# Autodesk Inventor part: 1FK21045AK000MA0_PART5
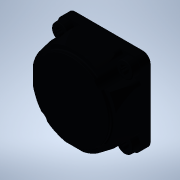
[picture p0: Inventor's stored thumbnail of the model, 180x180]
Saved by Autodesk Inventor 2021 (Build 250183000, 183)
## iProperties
Created: 2025-04
Part Number: 1FK21045AK000MA0_PART5
Material: Generic
Catalog Web Link: www.3dfindit.com
Description: -Servo synchronous motor
Document SubType Name: Modeling
Designer: psAdmin
Mass: 3.92604 g
Surface Area: 17.9521 cm^2
Volume: 3.92604 cm^3
Density: 1 g/cm^3
Appearance: PSOLRGB-48-56-69
Category: PARTsolutions
Title: 1FK21045AK000MA0_PART5
Author: Cadenas PARTsolutions
Comments: Servo synchronous motor
Sending System: PARTsolutions
Preprocessor: ST-DEVELOPER v19.3
PSOL_IDENT_0: {$CADENAS_DATA/23d-libs/siemens_ag/_cat_/3d/2f/1fk21045ak000ma0.prj},213 {VTYP=3D},{NB=1FK21045AK000
PSOL_IDENT_1: MA0_PART5},{LINA=1FK21045AK000MA0_PART5},{NN=1FK21045AK000MA0_PART5},{NOPRJ=TRUE},{DATE=19.08.2025 1
PSOL_IDENT_2: 4:00:34},{GEOMDATE=30.07.2025 02:01:24},{VERSION=},{LINEID=10},{WBVAR=},{WBNUMERIC=}  {NB=1FK21045AK
PSOL_IDENT_3: 000MA0_PART5},{LINA=1FK21045AK000MA0_PART5},{KT=DUMMY},{PREVIEW=../../../_pool_/a9/69/p_d211_xx_0081
PSOL_IDENT_4: 8j.png},{DESCSHORT=SIMOTICS S-1FK2 HD, SINAMICS S210 3AC 400V-480V, 1.7 Nm, 6000 rpm},{DESCLONG=SIMO
PSOL_IDENT_5: TICS S-1FK2 HD servo motor M0=2.4 Nm; PN = 1.07 kW at nN=6000 rpm (380-480 V); PN = 0.75 kW at nN=30
PSOL_IDENT_6: 00 rpm (200-240 V); degree of protection IP64; cylindrical shaft D19x40mm; absolute encoder 22-bit +
PSOL_IDENT_7: 12-bit multiturn (encoder AM22DQC); with OCC interface; plug size M17, rotatable; SIMOTICS S-1FK2 s
PSOL_IDENT_8: ervomotorfor a wide range of uses in industrial environments. SIMOTICS S‑1FK2 servomotors are compac
PSOL_IDENT_9: t synchronous motors with a high dynamic performance that set themselves apart as a result of their
PSOL_IDENT_10: high power density, degree of protection and overload capability. The motors are available in two va
PSOL_IDENT_11: riants: as High Dynamic variant (highest dynamic performance as a result of the low intrinsic moment
PSOL_IDENT_12: of inertia for applications demanding a high dynamic performance with low moved masses) - and as Co
PSOL_IDENT_13: mpact variant (precise and stable closed-loop control for medium up to large moved masses as a resul
PSOL_IDENT_14: t of a medium intrinsic moment of inertia). SIMOTICSS‑1FK2 servomotors fully exploit their strengths
PSOL_IDENT_15: in a system with the SINAMICSS210 frequency converter and simple connection using the one cable con
PSOL_IDENT_16: nection (OCC). Advantages include the short control and positioning times, fast and precise correcti
PSOL_IDENT_17: on of disturbing quantities as well as stable control with a high dynamic performance. The servo mot
PSOL_IDENT_18: ors can be configured to address a wide range of requirements. For example with and without holding
PSOL_IDENT_19: brake, IP64 or IP65 degree of protection, singleturn or multiturn absolute encoders - to name just a
PSOL_IDENT_20: few. Further, the servomotors are available in different shaft heights extending from 20 to 100. A
PSOL_IDENT_21: shaft sealing ring is available to achieve an IP65 degree of protection and for subsequent mounting
PSOL_IDENT_22: at the motor or as spare part. SIMOTICS - the optimum motor for each and every motion control applic
PSOL_IDENT_23: ation.},{INTNO=804766789342},{SUPPLIERALTNO=1FK2104-5AK00-0MA0},{MANUID=1FK21045AK000MA0},{MANUNAME=
PSOL_IDENT_24: Siemens},{MANUTYPEDESC=Synchronous motor 1FK2-HD 2,39 Nm},{AAU732=SIMOTICS},{AAO057=S-1FK2},{AAU734=
PSOL_IDENT_25: SIMOTICS S-1FK2 HD servo motor M0=2.4 Nm; PN = 1.07 kW at nN=6000 rpm (380-480 V); PN = 0.75 kW at n
PSOL_IDENT_26: N=3000 rpm (200-240 V); degree of protection IP64; cylindrical shaft D19x40mm; absolute encoder 22-b
PSOL_IDENT_27: it + 12-bit multiturn (encoder AM22DQC); with OCC interface; plug size M17, rotatable;},{AAW338=Sync
PSOL_IDENT_28: hronous motor 1FK2-HD 2,39 Nm},{AAO742=SIMOTICS},{AAO663=4042948691151},{NOCUPEROU=1},{PRICEQUANTITY=
PSOL_IDENT_29: 1},{QUANTITYMIN=1},{QUANTITYINT=1},{CTN=85015100},{COO=DE},{AAO676=1FK2104-5AK00-0MA0},{AAO677=Sieme
PSOL_IDENT_30: ns AG},{ORDERUNIT=C62},{CONTENTUNIT=C62}
NB: 1FK21045AK000MA0_PART5
NT: Servo synchronous motor
NBSYN: $MANUID._PART5
LINA: 1FK21045AK000MA0_PART5
CATALOG: SIEMENS
PREVIEW: ../../../_pool_/a9/69/p_d211_xx_00818j.png
DESCSHORT: SIMOTICS S-1FK2 HD, SINAMICS S210 3AC 400V-480V, 1.7 Nm, 6000 rpm
DESCLONG: SIMOTICS S-1FK2 HD servo motor M0=2.4 Nm; PN = 1.07 kW at nN=6000 rpm (380-480 V); PN = 0.75 kW at nN=3000 rpm (200-240 V); degree of protection IP64; cylindric
INTNO: 804766789342
SUPPLIERALTNO: 1FK2104-5AK00-0MA0
MANUID: 1FK21045AK000MA0
MANUNAME: Siemens
MANUTYPEDESC: Synchronous motor 1FK2-HD 2,39 Nm
AAU732: SIMOTICS
AAO057: S-1FK2
AAU734: SIMOTICS S-1FK2 HD servo motor M0=2.4 Nm; PN = 1.07 kW at nN=6000 rpm (380-480 V); PN = 0.75 kW at nN=3000 rpm (200-240 V); degree of protection IP64; cylindric
AAW338: Synchronous motor 1FK2-HD 2,39 Nm
AAO742: SIMOTICS
AAO663: 4042948691151.0
NOCUPEROU: 1
PRICEQUANTITY: 1
QUANTITYMIN: 1
QUANTITYINT: 1
CTN: 85015100
COO: DE
ARTICLENO: 1FK21045AK000MA0_PART5
BOMINFO: 1FK21045AK000MA0_PART5
CREATOR: CADENAS GmbH
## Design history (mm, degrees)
feature "2025_04_17_15_39_51_0665"
body "Solid1"
